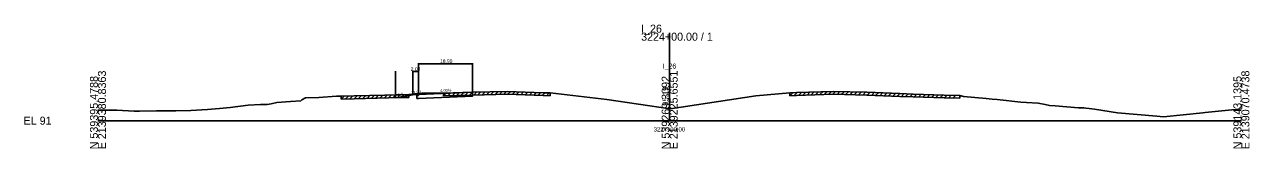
# Model space of a CAD drawing. Extents: x -13101 to 4803, y -924 to 22390.
# Drawn here: x 1974.3 to 2402.8, y 11990.3 to 12033.6 of the extents above; entities that cross this region are included whole.
import ezdxf

# ---------------------------------------------------------------- set-up
doc = ezdxf.new("R2010")
doc.units = 0
for name, color, linetype in [('RD_GPK_XS_Cell', 7, 'Continuous'), ('RD_XD_TX_Width', 7, 'Continuous'), ('RD_XS_Base', 7, 'Continuous'), ('RD_XS_EarthShd', 7, 'Continuous'), ('RD_XS_EwShp', 7, 'Continuous'), ('RD_XS_ExGround', 7, 'Continuous'), ('RD_XS_ExPaveRet', 7, 'Continuous'), ('RD_XS_OSBase', 7, 'Continuous'), ('RD_XS_Pave', 7, 'Continuous'), ('RD_XS_TieSlope', 7, 'Continuous'), ('RD_XS_TX_Baseline', 7, 'Continuous'), ('RD_XS_TX_Elev_EX', 7, 'Continuous'), ('RD_XS_TX_ShdSlope', 7, 'Continuous'), ('RD_XS_TX_Slope', 7, 'Continuous'), ('RD_XS_TX_Station', 7, 'Continuous')]:
    doc.layers.add(name, color=color, linetype=linetype)

msp = doc.modelspace()

# ---------------------------------------------------------------- linework, layer by layer
at = {"layer": 'RD_GPK_XS_Cell'}
for p, q in [((2200, 12000), (2200, 12030.71)), ((2000, 12000), (2200, 12000)), ((2200, 12000), (2400, 12000))]:
    msp.add_line(p, q, dxfattribs=at)
at = {"layer": 'RD_XD_TX_Width'}
for p, q in [((2104.1, 12017.34), (2104.1, 12009.39)), ((2110.1, 12017.34), (2110.1, 12009.23)), ((2112.1, 12017.14), (2110.1, 12017.14)), ((2112.1, 12020.1), (2112.1, 12009.39)), ((2112.1, 12019.9), (2131, 12019.9)), ((2112.1, 12017.34), (2112.1, 12009.39)), ((2131, 12020.1), (2131, 12010.15))]:
    msp.add_line(p, q, dxfattribs=at)
at = {"layer": 'RD_XS_Base'}
msp.add_line((2112.1, 12007.79), (2131, 12008.55), dxfattribs=at)
at = {"layer": 'RD_XS_EarthShd'}
msp.add_line((2112.1, 12009.19), (2110.1, 12009.03), dxfattribs=at)
at = {"layer": 'RD_XS_EwShp'}
msp.add_lwpolyline([(2112.1, 12009.19), (2110.1, 12009.03), (2104.1, 12008.03), (2104.1, 12009), (2105.69, 12009.04), (2108.77, 12009.13), (2109.75, 12009.2), (2111.85, 12009.45), (2112.62, 12009.54), (2113.4, 12009.55), (2117.76, 12009.59), (2120.94, 12009.64), (2131, 12009.95), (2131, 12009.55), (2131, 12008.55), (2112.1, 12007.79), (2111.6, 12007.77), (2111.6, 12008.77), (2112.1, 12008.79)], close=True, dxfattribs=at)
at = {"layer": 'RD_XS_ExGround'}
msp.add_lwpolyline([(2000, 12003.63), (2005.3, 12003.7), (2006.58, 12003.68), (2012.65, 12003.34), (2014.52, 12003.35), (2020.49, 12003.41), (2027.25, 12003.43), (2032.54, 12003.6), (2038.38, 12003.93), (2042.55, 12004.2), (2046.29, 12004.65), (2052.56, 12005.38), (2056.81, 12005.59), (2059.15, 12005.7), (2060.58, 12005.93), (2062.57, 12006.3), (2067.31, 12006.7), (2070.92, 12006.98), (2071.3, 12007.33), (2072.58, 12007.92), (2077.26, 12008.11), (2083.47, 12008.56), (2085.14, 12008.51), (2089.58, 12008.68), (2105.69, 12009.04), (2108.77, 12009.13), (2109.75, 12009.2), (2111.85, 12009.45), (2112.62, 12009.54), (2113.4, 12009.55), (2117.76, 12009.59), (2120.94, 12009.64), (2131.11, 12009.95), (2143.13, 12010.24), (2155.71, 12009.77), (2158.21, 12009.69), (2178.05, 12007.41), (2200.16, 12004.17), (2230.2, 12008.69), (2242.05, 12009.72), (2244.35, 12009.82), (2257.14, 12010.23), (2268.94, 12009.9), (2280.49, 12009.48), (2285.22, 12009.31), (2296.02, 12008.92), (2301.52, 12008.8), (2302.8, 12008.43), (2310.77, 12007.75), (2312.81, 12007.56), (2314.62, 12007.34), (2322.82, 12006.42), (2324.83, 12006.31), (2328.9, 12006.15), (2331.36, 12005.62), (2332.83, 12005.34), (2334.87, 12005.21), (2343.05, 12004.53), (2344.86, 12004.46), (2345.57, 12004.38), (2346.72, 12004.25), (2348.58, 12004.01), (2356.72, 12002.78), (2370.4, 12001.59), (2372.71, 12001.4), (2386.5, 12002.77), (2387.33, 12002.85), (2395.51, 12003.72), (2400, 12004.11)], dxfattribs=at)
at = {"layer": 'RD_XS_ExPaveRet'}
for p, q in [((2085.14, 12007.51), (2086.18, 12008.55)), ((2085.14, 12007.51), (2085.14, 12008.51)), ((2085.14, 12007.51), (2089.58, 12007.68)), ((2086.64, 12007.57), (2087.68, 12008.61)), ((2088.14, 12007.63), (2089.18, 12008.67)), ((2089.58, 12007.68), (2105.69, 12008.04)), ((2089.64, 12007.68), (2090.66, 12008.7)), ((2091.14, 12007.72), (2092.16, 12008.74)), ((2092.64, 12007.75), (2093.66, 12008.77)), ((2094.14, 12007.78), (2095.16, 12008.8)), ((2095.64, 12007.81), (2096.66, 12008.84)), ((2097.14, 12007.85), (2098.16, 12008.87)), ((2098.64, 12007.88), (2099.66, 12008.9)), ((2100.14, 12007.91), (2101.16, 12008.94)), ((2101.64, 12007.95), (2102.66, 12008.97)), ((2103.14, 12007.98), (2104.16, 12009)), ((2104.64, 12008.01), (2105.66, 12009.04)), ((2105.69, 12008.04), (2108.77, 12008.13)), ((2106.14, 12008.05), (2107.17, 12009.08)), ((2107.64, 12008.09), (2108.67, 12009.13)), ((2108.77, 12009.13), (2108.77, 12008.13)), ((2120.94, 12008.64), (2121.97, 12009.67)), ((2120.94, 12008.64), (2120.94, 12009.64)), ((2120.94, 12008.64), (2131.11, 12008.95)), ((2122.44, 12008.69), (2123.47, 12009.72)), ((2123.94, 12008.73), (2124.97, 12009.76)), ((2125.44, 12008.78), (2126.47, 12009.81)), ((2126.94, 12008.82), (2127.97, 12009.85)), ((2128.44, 12008.87), (2129.47, 12009.9)), ((2129.94, 12008.91), (2130.97, 12009.95)), ((2131.11, 12008.95), (2143.13, 12009.24)), ((2131.44, 12008.96), (2132.46, 12009.98)), ((2132.94, 12008.99), (2133.96, 12010.02)), ((2134.44, 12009.03), (2135.46, 12010.05)), ((2135.94, 12009.06), (2136.96, 12010.09)), ((2137.44, 12009.1), (2138.46, 12010.13)), ((2138.94, 12009.14), (2139.96, 12010.16)), ((2140.44, 12009.17), (2141.46, 12010.2)), ((2141.94, 12009.21), (2142.96, 12010.23)), ((2143.13, 12009.24), (2155.71, 12008.77)), ((2143.44, 12009.23), (2144.4, 12010.19)), ((2144.94, 12009.17), (2145.9, 12010.13)), ((2146.44, 12009.11), (2147.4, 12010.08)), ((2147.94, 12009.06), (2148.9, 12010.02)), ((2149.44, 12009), (2150.4, 12009.97)), ((2150.94, 12008.95), (2151.9, 12009.91)), ((2152.44, 12008.89), (2153.4, 12009.86)), ((2153.94, 12008.84), (2154.9, 12009.8)), ((2155.44, 12008.78), (2156.4, 12009.75)), ((2155.71, 12008.77), (2158.21, 12008.69)), ((2156.94, 12008.73), (2157.9, 12009.7)), ((2158.21, 12009.69), (2158.21, 12008.69)), ((2242.05, 12008.72), (2243.09, 12009.77)), ((2242.05, 12008.72), (2242.05, 12009.72)), ((2242.05, 12008.72), (2244.35, 12008.82)), ((2243.55, 12008.79), (2244.59, 12009.83)), ((2244.35, 12008.82), (2257.14, 12009.23)), ((2245.05, 12008.84), (2246.08, 12009.88)), ((2246.55, 12008.89), (2247.58, 12009.92)), ((2248.05, 12008.94), (2249.08, 12009.97)), ((2249.55, 12008.99), (2250.58, 12010.02)), ((2251.05, 12009.03), (2252.08, 12010.07)), ((2252.55, 12009.08), (2253.58, 12010.11)), ((2254.05, 12009.13), (2255.08, 12010.16)), ((2255.55, 12009.18), (2256.58, 12010.21)), ((2257.05, 12009.22), (2258.02, 12010.2)), ((2257.14, 12009.23), (2268.94, 12008.9)), ((2258.55, 12009.19), (2259.52, 12010.16)), ((2260.05, 12009.14), (2261.02, 12010.12)), ((2261.55, 12009.1), (2262.52, 12010.08)), ((2263.05, 12009.06), (2264.02, 12010.03)), ((2264.55, 12009.02), (2265.52, 12009.99)), ((2266.05, 12008.98), (2267.02, 12009.95)), ((2267.55, 12008.93), (2268.52, 12009.91)), ((2268.94, 12008.9), (2280.49, 12008.48)), ((2269.05, 12008.89), (2270.01, 12009.86)), ((2270.55, 12008.84), (2271.51, 12009.8)), ((2272.05, 12008.78), (2273.01, 12009.75)), ((2273.55, 12008.73), (2274.51, 12009.7)), ((2275.05, 12008.68), (2276.01, 12009.64)), ((2276.55, 12008.62), (2277.51, 12009.59)), ((2278.05, 12008.57), (2279.01, 12009.54)), ((2279.55, 12008.52), (2280.51, 12009.48)), ((2280.49, 12008.48), (2285.22, 12008.31)), ((2281.05, 12008.46), (2282.01, 12009.43)), ((2282.55, 12008.41), (2283.51, 12009.37)), ((2284.05, 12008.35), (2285.01, 12009.32)), ((2285.22, 12008.31), (2296.02, 12007.92)), ((2285.55, 12008.3), (2286.51, 12009.26)), ((2287.05, 12008.24), (2288.01, 12009.21)), ((2288.55, 12008.19), (2289.51, 12009.15)), ((2290.05, 12008.13), (2291.01, 12009.1)), ((2291.55, 12008.08), (2292.51, 12009.04)), ((2293.05, 12008.02), (2294.01, 12008.99)), ((2294.55, 12007.97), (2295.51, 12008.93)), ((2296.02, 12007.92), (2301.52, 12007.8)), ((2296.05, 12007.91), (2297.03, 12008.89)), ((2297.55, 12007.88), (2298.53, 12008.86)), ((2299.05, 12007.85), (2300.03, 12008.83)), ((2301.52, 12008.8), (2301.52, 12007.8))]:
    msp.add_line(p, q, dxfattribs=at)
at = {"layer": 'RD_XS_OSBase'}
for p, q in [((2111.6, 12008.77), (2112.1, 12008.79)), ((2111.6, 12007.77), (2111.6, 12008.77)), ((2112.1, 12007.79), (2111.6, 12007.77)), ((2112.1, 12008.79), (2112.1, 12009.19)), ((2131, 12009.55), (2131, 12009.95)), ((2131, 12008.55), (2131, 12009.55))]:
    msp.add_line(p, q, dxfattribs=at)
at = {"layer": 'RD_XS_Pave'}
msp.add_line((2112.1, 12009.19), (2131, 12009.95), dxfattribs=at)
at = {"layer": 'RD_XS_TieSlope'}
for p, q in [((2110.1, 12009.03), (2104.1, 12008.03)), ((2104.1, 12008.03), (2104.1, 12009))]:
    msp.add_line(p, q, dxfattribs=at)

# ---------------------------------------------------------------- texts
at = {"layer": 'RD_GPK_XS_Cell'}
for s, p in [('I_26', (2190, 12030.71)), ('3224+00.00 / 1', (2190, 12027.91)), ('EL 91', (1974, 11998.6))]:
    msp.add_text(s, height=2.8, dxfattribs=at).set_placement(p)
for s, p in [('E 2139380.8363', (2002.8, 11990)), ('E 2139225.6551', (2202.8, 11990)), ('E 2139070.4738', (2402.8, 11990)), ('N 539395.4788', (2000, 11990)), ('N 539269.3092', (2200, 11990)), ('N 539143.1395', (2400, 11990))]:
    msp.add_text(s, height=2.8, rotation=90, dxfattribs=at).set_placement(p)
at = {"layer": 'RD_XD_TX_Width'}
for s, p in [('18.90', (2119.68, 12020.15)), ('2.00', (2109.42, 12017.39))]:
    msp.add_text(s, height=1.25, dxfattribs=at).set_placement(p)
at = {"layer": 'RD_XS_TX_Baseline'}
msp.add_text('I_26', height=1.75, dxfattribs=at).set_placement((2197.6, 12018.19))
at = {"layer": 'RD_XS_TX_Elev_EX'}
msp.add_text('95.19', height=2, rotation=90, dxfattribs=at).set_placement((2199.5, 12005.19))
at = {"layer": 'RD_XS_TX_ShdSlope'}
msp.add_text('12.5:1', height=1, rotation=4.5739, dxfattribs=at).set_placement((2109.57, 12009.24))
msp.add_text('12.5:1', height=1, rotation=4.5739, dxfattribs=at).set_placement((2109.57, 12009.24))
at = {"layer": 'RD_XS_TX_Slope'}
for s, rotation, p in [('6:1', 9.4623, (2104.99, 12008.5)), ('4.00%', 2.2906, (2119.73, 12010))]:
    msp.add_text(s, height=1, rotation=rotation, dxfattribs=at).set_placement(p)
at = {"layer": 'RD_XS_TX_Station'}
msp.add_text('3224+00.00', height=1.5, dxfattribs=at).set_placement((2194.41, 11996.19))

doc.saveas('drawing.dxf')
